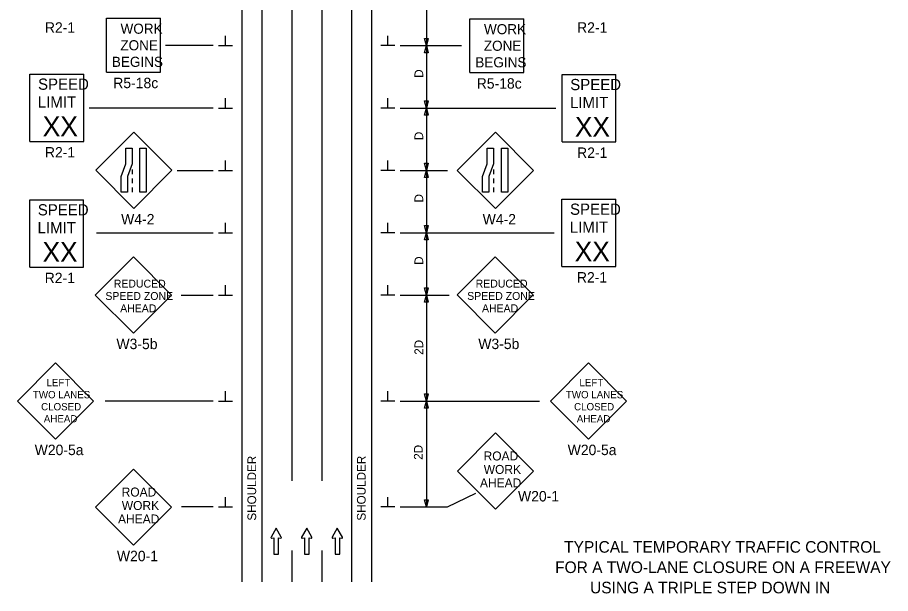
# Model space of a CAD drawing. Extents: x 16504 to 18480, y 5523 to 6928.
# Drawn here: x 16736 to 17437, y 5993 to 6455 of the extents above; entities that cross this region are included whole.
import ezdxf

# ---------------------------------------------------------------- set-up
doc = ezdxf.new("R2010")
doc.units = 0
for name, color, linetype in [('ALI_LEGAL_EX', 7, 'Continuous'), ('BORDER', 7, 'Continuous'), ('MT_SCRATCH_LEVEL_E', 7, 'Continuous'), ('PAVT_EDGE_EX', 7, 'Continuous'), ('TRAFFIC_SIGNS_PR', 7, 'Continuous'), ('TYPICAL_TEXT_DIMEN_PR', 7, 'Continuous')]:
    doc.layers.add(name, color=color, linetype=linetype)

msp = doc.modelspace()

# ---------------------------------------------------------------- linework, layer by layer
at = {"layer": 'ALI_LEGAL_EX'}
for p, q in [((16956.63, 6927.83), (16956.63, 6083.69)), ((16980.63, 6927.83), (16980.63, 6083.69))]:
    msp.add_line(p, q, dxfattribs=at)
for points in [[(16956.63, 6427.83), (16956.63, 6402.83)], [(16980.63, 6427.83), (16980.63, 6402.83)], [(16956.63, 6327.83), (16956.63, 6302.83)], [(16980.63, 6327.83), (16980.63, 6302.83)], [(16956.63, 6227.83), (16956.63, 6202.83)], [(16980.63, 6227.83), (16980.63, 6202.83)], [(16956.63, 6127.83), (16956.63, 6102.83)], [(16980.63, 6127.83), (16980.63, 6102.83)], [(16956.63, 6027.83), (16956.63, 6002.83)], [(16980.63, 6027.83), (16980.63, 6002.83)]]:
    msp.add_lwpolyline(points, dxfattribs=at)
at = {"layer": 'MT_SCRATCH_LEVEL_E'}
for p, q in [((16944.07, 6045.7), (16939.96, 6038.46)), ((16948.22, 6038.46), (16944.07, 6045.7)), ((16968.6, 6045.7), (16964.49, 6038.46)), ((16972.75, 6038.46), (16968.6, 6045.7)), ((16993.16, 6045.7), (16989.05, 6038.46)), ((16997.31, 6038.46), (16993.16, 6045.7)), ((16940.44, 6037.78), (16942.22, 6038.09)), ((16942.22, 6038.09), (16942.22, 6024.84)), ((16945.96, 6024.84), (16945.96, 6038.09)), ((16945.96, 6038.09), (16947.74, 6037.78)), ((16964.97, 6037.78), (16966.75, 6038.09)), ((16966.75, 6038.09), (16966.75, 6024.84)), ((16970.49, 6024.84), (16970.49, 6038.09)), ((16970.49, 6038.09), (16972.27, 6037.78)), ((16989.53, 6037.78), (16991.31, 6038.09)), ((16991.31, 6038.09), (16991.31, 6024.84)), ((16995.05, 6024.84), (16995.05, 6038.09)), ((16995.05, 6038.09), (16996.83, 6037.78)), ((16942.22, 6024.84), (16945.96, 6024.84)), ((16966.75, 6024.84), (16970.49, 6024.84)), ((16991.31, 6024.84), (16995.05, 6024.84))]:
    msp.add_line(p, q, dxfattribs=at)
for centre, start, end in [((16940.37, 6038.24), 150.42484, 279.96381), ((16947.81, 6038.24), 260.03619, 29.77312), ((16964.9, 6038.24), 150.42484, 279.96381), ((16972.34, 6038.24), 260.03619, 29.77312), ((16989.46, 6038.24), 150.42484, 279.96381), ((16996.9, 6038.24), 260.03619, 29.77312)]:
    msp.add_arc(centre, 0.463, start, end, dxfattribs=at)
at = {"layer": 'PAVT_EDGE_EX'}
for p, q in [((16916.63, 6919.19), (16916.63, 6002.83)), ((16932.63, 6919.19), (16932.63, 6002.83)), ((17004.63, 6919.19), (17004.63, 6002.83)), ((17020.63, 6919.19), (17020.63, 6002.83))]:
    msp.add_line(p, q, dxfattribs=at)
at = {"layer": 'TRAFFIC_SIGNS_PR'}
for p, q in [((16807.92, 6411.52), (16807.92, 6454.72)), ((16807.92, 6454.72), (16851.12, 6454.72)), ((16851.12, 6411.52), (16851.12, 6454.72)), ((17099.64, 6411.14), (17099.64, 6454.34)), ((17099.64, 6454.34), (17142.84, 6454.34)), ((17142.84, 6411.14), (17142.84, 6454.34)), ((16746.47, 6409.93), (16789.67, 6409.93)), ((16746.47, 6355.93), (16746.47, 6409.93)), ((16789.67, 6355.93), (16789.67, 6409.93)), ((16807.92, 6411.52), (16851.12, 6411.52)), ((17099.64, 6411.14), (17142.84, 6411.14)), ((17173.61, 6409.6), (17216.81, 6409.6)), ((17173.61, 6355.6), (17173.61, 6409.6)), ((17216.81, 6355.6), (17216.81, 6409.6)), ((16829.81, 6363.36), (16799.26, 6332.81)), ((16860.35, 6332.81), (16829.81, 6363.36)), ((17120, 6363.31), (17089.45, 6332.76)), ((17150.54, 6332.76), (17120, 6363.31)), ((16746.47, 6355.93), (16789.67, 6355.93)), ((17173.61, 6355.6), (17216.81, 6355.6)), ((16799.26, 6332.81), (16829.81, 6302.27)), ((16828.4, 6333.37), (16828.4, 6329.77)), ((16829.81, 6302.27), (16860.35, 6332.81)), ((17089.45, 6332.76), (17120, 6302.21)), ((17118.59, 6333.31), (17118.59, 6329.71)), ((17120, 6302.21), (17150.54, 6332.76)), ((16828.4, 6326.17), (16828.4, 6322.57)), ((17118.59, 6326.11), (17118.59, 6322.51)), ((16828.4, 6318.97), (16828.4, 6315.37)), ((17118.59, 6318.91), (17118.59, 6315.31)), ((16746.27, 6309.16), (16789.47, 6309.16)), ((16746.27, 6255.16), (16746.27, 6309.16)), ((16789.47, 6255.16), (16789.47, 6309.16)), ((17173.46, 6309.62), (17216.66, 6309.62)), ((17173.46, 6255.62), (17173.46, 6309.62)), ((17216.66, 6255.62), (17216.66, 6309.62)), ((16829.44, 6263.32), (16798.89, 6232.77)), ((16859.98, 6232.77), (16829.44, 6263.32)), ((17119.86, 6263.36), (17089.32, 6232.81)), ((17150.41, 6232.81), (17119.86, 6263.36)), ((16746.27, 6255.16), (16789.47, 6255.16)), ((17173.46, 6255.62), (17216.66, 6255.62)), ((16798.89, 6232.77), (16829.44, 6202.22)), ((16829.44, 6202.22), (16859.98, 6232.77)), ((17089.32, 6232.81), (17119.86, 6202.26)), ((17119.86, 6202.26), (17150.41, 6232.81)), ((16766.97, 6178.31), (16736.42, 6147.76)), ((16797.52, 6147.76), (16766.97, 6178.31)), ((17194.77, 6178.31), (17164.22, 6147.76)), ((17225.31, 6147.76), (17194.77, 6178.31)), ((16736.42, 6147.76), (16766.97, 6117.21)), ((16766.97, 6117.21), (16797.52, 6147.76)), ((17164.22, 6147.76), (17194.77, 6117.21)), ((17194.77, 6117.21), (17225.31, 6147.76)), ((17120.06, 6122.15), (17089.52, 6091.6)), ((17150.61, 6091.6), (17120.06, 6122.15)), ((16829.56, 6093.2), (16799.02, 6062.65)), ((16860.11, 6062.65), (16829.56, 6093.2)), ((17089.52, 6091.6), (17120.06, 6061.06)), ((17120.06, 6061.06), (17150.61, 6091.6)), ((16799.02, 6062.65), (16829.56, 6032.11)), ((16829.56, 6032.11), (16860.11, 6062.65))]:
    msp.add_line(p, q, dxfattribs=at)
for points in [[(16828.4, 6350.52), (16828.4, 6337.94), (16824.64, 6327.95), (16824.64, 6315.37), (16819.59, 6315.37), (16819.59, 6327.95), (16823.35, 6337.94), (16823.35, 6350.52)], [(16839.81, 6350.52), (16839.81, 6315.37), (16834.75, 6315.37), (16834.75, 6350.52)], [(17118.59, 6350.47), (17118.59, 6337.89), (17114.83, 6327.89), (17114.83, 6315.31), (17109.78, 6315.31), (17109.78, 6327.89), (17113.54, 6337.89), (17113.54, 6350.47)], [(17130, 6350.47), (17130, 6315.31), (17124.94, 6315.31), (17124.94, 6350.47)]]:
    msp.add_lwpolyline(points, close=True, dxfattribs=at)
at = {"layer": 'TYPICAL_TEXT_DIMEN_PR'}
for p, q in [((17064.63, 6482.76), (17064.63, 6432.76)), ((16903.51, 6432.76), (16903.51, 6440.55)), ((17033.76, 6432.76), (17033.76, 6440.55)), ((17064.63, 6432.76), (17063.06, 6438.62)), ((17063.06, 6438.62), (17064.63, 6438.62)), ((17064.63, 6438.62), (17066.2, 6438.62)), ((17066.2, 6438.62), (17064.63, 6432.76)), ((16893.63, 6432.76), (16855.28, 6432.76)), ((16897.88, 6432.76), (16909.13, 6432.76)), ((17039.38, 6432.76), (17028.13, 6432.76)), ((17043.63, 6432.76), (17092.92, 6432.76)), ((17063.06, 6426.9), (17064.63, 6432.76)), ((17064.63, 6426.9), (17063.06, 6426.9)), ((17064.63, 6432.76), (17066.2, 6426.9)), ((17064.63, 6432.76), (17064.63, 6382.76)), ((17066.2, 6426.9), (17064.63, 6426.9)), ((16903.51, 6382.76), (16903.51, 6390.55)), ((17033.76, 6382.76), (17033.76, 6390.55)), ((17064.63, 6382.76), (17063.06, 6388.62)), ((17063.06, 6388.62), (17064.63, 6388.62)), ((17064.63, 6388.62), (17066.2, 6388.62)), ((17066.2, 6388.62), (17064.63, 6382.76)), ((16893.63, 6382.76), (16794.04, 6382.76)), ((16897.88, 6382.76), (16909.13, 6382.76)), ((17039.38, 6382.76), (17028.13, 6382.76)), ((17043.63, 6382.76), (17168.63, 6382.76)), ((17063.06, 6376.9), (17064.63, 6382.76)), ((17064.63, 6382.76), (17064.63, 6332.76)), ((17064.63, 6382.76), (17066.2, 6376.9)), ((17064.63, 6376.9), (17063.06, 6376.9)), ((17066.2, 6376.9), (17064.63, 6376.9)), ((16903.51, 6332.76), (16903.51, 6340.55)), ((17033.76, 6332.76), (17033.76, 6340.55)), ((17064.63, 6332.76), (17063.06, 6338.62)), ((17063.06, 6338.62), (17064.63, 6338.62)), ((17064.63, 6338.62), (17066.2, 6338.62)), ((17066.2, 6338.62), (17064.63, 6332.76)), ((16864.64, 6332.76), (16893.63, 6332.76)), ((16897.88, 6332.76), (16909.13, 6332.76)), ((17039.38, 6332.76), (17028.13, 6332.76)), ((17043.63, 6332.76), (17081.49, 6332.76)), ((17063.06, 6326.9), (17064.63, 6332.76)), ((17064.63, 6332.76), (17066.2, 6326.9)), ((17064.63, 6332.76), (17064.63, 6282.76)), ((17064.63, 6326.9), (17063.06, 6326.9)), ((17066.2, 6326.9), (17064.63, 6326.9)), ((16903.51, 6282.76), (16903.51, 6290.55)), ((17033.76, 6282.76), (17033.76, 6290.55)), ((17064.63, 6282.76), (17063.06, 6288.62)), ((17063.06, 6288.62), (17064.63, 6288.62)), ((17064.63, 6288.62), (17066.2, 6288.62)), ((17066.2, 6288.62), (17064.63, 6282.76)), ((16799.76, 6282.76), (16893.63, 6282.76)), ((16897.88, 6282.76), (16909.13, 6282.76)), ((17039.38, 6282.76), (17028.13, 6282.76)), ((17043.63, 6282.76), (17167.18, 6282.76)), ((17063.06, 6276.9), (17064.63, 6282.76)), ((17064.63, 6282.76), (17064.63, 6232.76)), ((17064.63, 6282.76), (17066.2, 6276.9)), ((17064.63, 6276.9), (17063.06, 6276.9)), ((17066.2, 6276.9), (17064.63, 6276.9)), ((16903.51, 6232.76), (16903.51, 6240.55)), ((17033.76, 6232.76), (17033.76, 6240.55)), ((17064.63, 6232.76), (17063.06, 6238.62)), ((17063.06, 6238.62), (17064.63, 6238.62)), ((17064.63, 6238.62), (17066.2, 6238.62)), ((17066.2, 6238.62), (17064.63, 6232.76)), ((16867.72, 6232.76), (16893.63, 6232.76)), ((16897.88, 6232.76), (16909.13, 6232.76)), ((17039.38, 6232.76), (17028.13, 6232.76)), ((17043.63, 6232.76), (17082.8, 6232.76)), ((17063.06, 6226.9), (17064.63, 6232.76)), ((17064.63, 6232.76), (17064.63, 6147.76)), ((17064.63, 6232.76), (17066.2, 6226.9)), ((17064.63, 6226.9), (17063.06, 6226.9)), ((17066.2, 6226.9), (17064.63, 6226.9)), ((16903.51, 6147.76), (16903.51, 6155.55)), ((17033.76, 6147.76), (17033.76, 6155.55)), ((17064.63, 6147.76), (17063.06, 6153.62)), ((17063.06, 6153.62), (17064.63, 6153.62)), ((17064.63, 6153.62), (17066.2, 6153.62)), ((17066.2, 6153.62), (17064.63, 6147.76)), ((16893.63, 6147.76), (16806.83, 6147.76)), ((16897.88, 6147.76), (16909.13, 6147.76)), ((17039.38, 6147.76), (17028.13, 6147.76)), ((17043.63, 6147.76), (17155.33, 6147.76)), ((17063.06, 6141.9), (17064.63, 6147.76)), ((17064.63, 6147.76), (17064.63, 6062.76)), ((17064.63, 6147.76), (17066.2, 6141.9)), ((17064.63, 6141.9), (17063.06, 6141.9)), ((17066.2, 6141.9), (17064.63, 6141.9)), ((16903.51, 6062.76), (16903.51, 6070.55)), ((17033.76, 6062.76), (17033.76, 6070.55)), ((17081.66, 6062.76), (17104.25, 6073.86)), ((16893.63, 6062.76), (16867.96, 6062.76)), ((16897.88, 6062.76), (16909.13, 6062.76)), ((17039.38, 6062.76), (17028.13, 6062.76)), ((17043.63, 6062.76), (17081.66, 6062.76)), ((17064.63, 6062.76), (17063.06, 6068.62)), ((17063.06, 6068.62), (17064.63, 6068.62)), ((17064.63, 6068.62), (17066.2, 6068.62)), ((17066.2, 6068.62), (17064.63, 6062.76))]:
    msp.add_line(p, q, dxfattribs=at)

# ---------------------------------------------------------------- texts
at = {"layer": 'BORDER'}
for s, p in [('TYPICAL TEMPORARY TRAFFIC CONTROL', (17175.21, 6026.08)), ('FOR A TWO-LANE CLOSURE ON A FREEWAY', (17167.99, 6009.78)), ('USING A TRIPLE STEP DOWN IN', (17196.04, 5993.48))]:
    msp.add_text(s, height=9.3, dxfattribs=at).set_placement(p)
at = {"layer": 'TRAFFIC_SIGNS_PR'}
for s, height, p in [('R2-1', 8.37, (16758.44, 6443.15)), ('WORK', 8.119, (16819.16, 6442.31)), ('WORK', 8.119, (17110.88, 6441.93)), ('R2-1', 8.37, (17185.62, 6443.15)), ('ZONE', 8.119, (16819.03, 6429.02)), ('ZONE', 8.119, (17110.75, 6428.64)), ('BEGINS', 8.119, (16812.2, 6415.74)), ('BEGINS', 8.119, (17103.92, 6415.36)), ('SPEED', 9, (16752.96, 6397.4)), ('R5-18c', 8.37, (16813.33, 6398.65)), ('R5-18c', 8.37, (17105.05, 6398.27)), ('SPEED', 9, (17180.1, 6397.07)), ('LIMIT', 9, (16752.77, 6383)), ('LIMIT', 9, (17179.92, 6382.67)), ('XX', 15.785, (16756.72, 6360.16)), ('XX', 15.785, (17183.86, 6359.83)), ('R2-1', 8.37, (16758.48, 6343.06)), ('R2-1', 8.37, (17185.62, 6342.73)), ('SPEED', 9, (16752.75, 6296.63)), ('SPEED', 9, (17179.95, 6297.09)), ('W4-2', 8.37, (16819.64, 6289.4)), ('W4-2', 8.37, (17109.82, 6289.35)), ('LIMIT', 9, (16752.57, 6282.23)), ('LIMIT', 9, (17179.77, 6282.69)), ('XX', 15.785, (16756.52, 6259.39)), ('XX', 15.785, (17183.71, 6259.85)), ('R2-1', 8.37, (17185.47, 6242.75)), ('R2-1', 8.37, (16758.28, 6242.29)), ('REDUCED', 6.3, (16813.75, 6238.74)), ('REDUCED', 6.3, (17104.18, 6238.78)), ('SPEED ZONE', 6.3, (16806.99, 6228.84)), ('SPEED ZONE', 6.3, (17097.42, 6228.88)), ('AHEAD', 6.3, (16818.87, 6218.94)), ('AHEAD', 6.3, (17109.3, 6218.98)), ('W3-5b', 8.37, (16815.88, 6189.35)), ('W3-5b', 8.37, (17106.31, 6189.39)), ('LEFT', 5.85, (16759.7, 6159.61)), ('LEFT', 5.85, (17187.5, 6159.61)), ('TWO LANES', 5.85, (16748.81, 6149.94)), ('TWO LANES', 5.85, (17176.61, 6149.94)), ('CLOSED', 5.85, (16755.4, 6140.26)), ('CLOSED', 5.85, (17183.19, 6140.26)), ('AHEAD', 5.85, (16757.59, 6130.59)), ('AHEAD', 5.85, (17185.38, 6130.59)), ('W20-5a', 8.37, (16750.25, 6104.35)), ('W20-5a', 8.37, (17178.05, 6104.35)), ('ROAD', 7.2, (17110.55, 6100.08)), ('WORK', 7.2, (17110.67, 6089.28)), ('AHEAD', 7.2, (17107.64, 6078.48)), ('ROAD', 7.2, (16820.05, 6071.13)), ('W20-1', 8.37, (17138.19, 6067.2)), ('WORK', 7.2, (16820.17, 6060.33)), ('AHEAD', 7.2, (16817.15, 6049.53)), ('W20-1', 8.37, (16816.26, 6019.24))]:
    msp.add_text(s, height=height, dxfattribs=at).set_placement(p)
at = {"layer": 'TYPICAL_TEXT_DIMEN_PR'}
for s, p in [('D', (17062.08, 6406.98)), ('D', (17062.08, 6356.98)), ('D', (17062.08, 6306.98)), ('D', (17062.08, 6256.98)), ('2D', (17062.08, 6184.83)), ('2D', (17061.64, 6100.62)), ('SHOULDER', (16928.01, 6051.81)), ('SHOULDER', (17015.91, 6051.81))]:
    msp.add_text(s, height=7, rotation=90, dxfattribs=at).set_placement(p)

doc.saveas('drawing.dxf')
